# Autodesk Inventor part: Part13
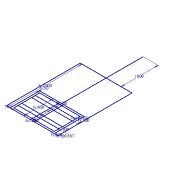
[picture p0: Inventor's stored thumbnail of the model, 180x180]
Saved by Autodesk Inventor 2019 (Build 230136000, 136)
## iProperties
Created: 2018-04
Part Number: Part13
Material: 一般
Document SubType Name: Modeling
Designer: ADJ
Density: 1 g/cm^3
Appearance: 既定
Author: ADJ
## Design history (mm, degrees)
sketch "スケッチ1"
  geometry: L1 (-600, 0)-(600, 0); L2 (600, 0)-(600, 800); L3 (600, 800)-(-600, 800); L4 (-600, 800)-(-600, 0); L5 (-550, 633.333)-(550, 633.333); L6 (550, 533.333)-(-550, 533.333); L7 (-550, 266.667)-(550, 266.667); L8 (550, 166.667)-(-550, 166.667); L9 (-50, 800)-(-50, 0); L10 (50, 800)-(50, 0); L11 (0, 0)-(0, 800); L12 (-550, 750)-(550, 750); L13 (550, 750)-(550, 50); L14 (550, 50)-(-550, 50); L15 (-550, 50)-(-550, 750); L16 (-700, 0)-(700, 0); L17 (700, 0)-(700, 2000); L18 (700, 2000)-(-700, 2000); L19 (-700, 2000)-(-700, 0); L20 (0, 800)-(0, 3000); 5 further points
  constraints: 40 end point, 21 point on line, 9 perpendicular, 6 parallel, 2 horizontal, 2 midpoint, 1 coincident, 1 collinear, 4 other
  dimensions: "d0" = 1200 distance of L1.start L1.end (= 水門幅); "d1" = 800 distance of L1.end L2.end (= 水門高さ); "d2" = 100 distance between parallel lines of L5 L6 (= 水門補強厚); "d3" = 100 distance between parallel lines of L7 L8 (= 水門補強厚); "d4" = 166.66667 distance between parallel lines of L8 L1 (= 補強サイドからの距離); "d5" = 166.66667 distance between parallel lines of L3 L5 (= 補強サイドからの距離); "d6" = 100 distance between parallel lines of L10 L9 (= 水門補強厚); "d7" = 50 distance between parallel lines of L3 L12 (= 水門周囲厚); "d25" = 2000 distance of L16.end L17.end (= ゲートフレーム高さ); "d26" = 100 distance between parallel lines of L19 L4; "d27" = 100 distance between parallel lines of L17 L2 (= d26); "d29" = 1000 distance from line of L20.end L18
node "Mech_Plane"
node "ソリッド1"
other parameters: "水門幅" = 1200 [user parameter; used in 1 equation term], "水門高さ" = 800 [user parameter; used in 1 equation term], "水門補強厚" = 100 [user parameter; used in 3 equation terms], "補強サイドからの距離" = 166.66667 (= -0.666667 x d7 + 0.333333 x d1 - 0.666667 x d2) [user parameter; used in 2 equation terms], "水門周囲厚" = 50 [user parameter; used in 1 equation term], "ゲートフレーム高さ" = 2000 [user parameter; used in 1 equation term]
